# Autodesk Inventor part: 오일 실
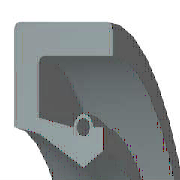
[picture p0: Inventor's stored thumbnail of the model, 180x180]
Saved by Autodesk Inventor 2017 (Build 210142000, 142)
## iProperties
IsCustomPart: 1
Created: 2015-12
Part Number: 오일 실
Material: 고무
Description: 오일-실
Document SubType Name: Modeling
Standard: KS B 2804
Designer: mdu
Standards Organization: KS
Language: ko-KR
Size Designation: S - 15 30 7
Categories: <MemberInstance><Categories><Category DisplayName="샤프트 부품" InternalName="7f7aeb1f-a693-4053-b835-cee3144e0d98" Mnemonic="SHFT"><Category DisplayName="실링" Intern
Density: 0.93 g/cm^3
Appearance: 고무 - 검은색 - 버전 1.1
Author: mdu
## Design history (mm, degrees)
revolve "본체" stored, may be unused: angle "d17" = 90 deg
revolve "스프링1" stored, may be unused: angle "d18" = 90 deg
body "Solid1"
sketch "스케치1"
  geometry: L1 (0, 15)-(7, 15); L2 (7, 15)-(7, 13.75); L3 (7, 13.75)-(1.75, 13.75); L4 (0, 15)-(0, 9.6); L5 (0, 9.6)-(1.75, 9.25); L6 (1.75, 9.25)-(4.9, 7.5); L7 (4.9, 7.5)-(0, 7.5); L8 (6.3, 8.375)-(6.3, 9.6); L9 (0, 0)-(9.586, 0) reference; L10 (4.9, 7.5)-(6.3, 8.375); L11 (0, 18)-(0, -3) reference; L12 (-1.917, 0)-(11.503, 0) reference; L13 (4.2, 9.6)-(1.75, 10.09); L14 (1.75, 10.09)-(1.75, 13.75); L15 (6.3, 9.6)-(5.6, 9.6); C1 r 0.455 at (4.9, 9.6); A1 r 0.7 centre (4.9, 9.6) between (5.6, 9.6) and (4.2, 9.6)
  constraints: 26 end point, 5 horizontal alignment, 4 perpendicular, 2 centre point, 2 collinear, 2 horizontal, 2 parallel, 2 point on circle, 2 point on line, 2 vertical alignment, 1 coincident
  dimensions: "d0" = 30 diameter of L1 L9 (= SD2); "d1" = 16.75 diameter of L8.start L9 (= ABDM); "d2" = 1.25 distance of L1.end L2.end (computed from SD); "d3" = 0.91 diameter of C1 (= SPDI); "d4" = 1.4 diameter of A1 (= SPDA); "d5" = 15 diameter of L6.end L9 (= NND); "d6" = 18.5 diameter of L5.end L9 (= TKDM); "d7" = 19.2 diameter of L4.end L9 (= HLDM); "d8" = 4.9 distance from line of C1.centre L4 (= SPDST); "d9" = 6.3 distance between parallel lines of L8 L4 (= SDI); "d10" = 7 distance between parallel lines of L2 L4 (= SWDT); "d12" = 1.75 distance between parallel lines of L14 L4 (= SD)
fillet "모깎기1" dims "d11" = 0.3 (= RR)
other parameters: "SD2" = 30 [user parameter; used in 1 equation term], "SWDT" = 7 [user parameter; used in 1 equation term], "RR" = 0.3 [user parameter; used in 1 equation term], "SD" = 1.75 [user parameter; used in 2 equation terms], "NND" = 15 [user parameter; used in 1 equation term], "SPDA" = 1.4 [user parameter; used in 1 equation term], "SPDI" = 0.91 [user parameter; used in 1 equation term], "TKDM" = 18.5 [user parameter; used in 1 equation term], "HLDM" = 19.2 [user parameter; used in 1 equation term], "ABDM" = 16.75 [user parameter; used in 1 equation term], "SDI" = 6.3 [user parameter; used in 1 equation term], "SPDST" = 4.9 [user parameter; used in 1 equation term], "d13" = 0, "d14" = 0, "d15" = 0, "LAB" = 0.35 [user parameter]
